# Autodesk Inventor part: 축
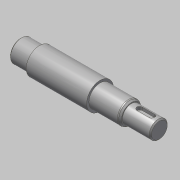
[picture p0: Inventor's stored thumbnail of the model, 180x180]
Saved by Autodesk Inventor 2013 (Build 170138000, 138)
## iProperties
Created: 2016-06
Part Number: 축
Material: 강철, 연강
Document SubType Name: Modeling
Designer: mduedu
Density: 7.86 g/cm^3
Author: mduedu
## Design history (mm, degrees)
sketch "스케치1"
  geometry: L1 (-62, 0)-(62, 0); L2 (-62, 0)-(-62, 10); L3 (-62, 10)-(-45, 10); L4 (-45, 10)-(-45, 12); L5 (-45, 12)-(9, 12); L6 (9, 12)-(9, 10); L7 (9, 10)-(37, 10); L8 (37, 10)-(37, 8); L9 (37, 8)-(62, 8); L10 (62, 8)-(62, 0); 2 further points
  constraints: 20 end point, 5 parallel, 2 perpendicular, 1 coincident, 1 collinear, 1 horizontal, 1 midpoint, 1 vertical
  dimensions: "d0" = 124 distance of L1.start L1.end; "d2" = 16 diameter of L9 L1; "d3" = 20 diameter of L7 L1; "d4" = 24 diameter of L5 L1; "d5" = 20 diameter of L3 L1; "d6" = 17 distance of L2.end L3.end; "d7" = 25 distance of L8.end L9.end; "d8" = 53 distance from line of L5.end L10
revolve "회전1" sketch "스케치1" stored, may be unused: angle "d9" = 90 deg
chamfer "모따기1" distance "d10" = 2; stored, may be unused: second distance "d11" = 2, angle "d12" = 30 deg
fillet "모깎기1" dims "d13" = 2
node "작업 평면1"
sketch "스케치2"
  geometry: L1 (-5, 2.5)-(6, 2.5); L2 (6, -2.5)-(-5, -2.5); L3 (-5, 0)-(6, 0); L4 (-12.5, 8.845)-(-12.5, -8.845) reference; A1 r 2.5 centre (-5, 0) between (-5, 2.5) and (-5, -2.5); A2 r 2.5 centre (6, 0) between (6, -2.5) and (6, 2.5); 1 further point
  constraints: 6 end point, 4 point on circle, 3 tangent, 2 centre point, 2 parallel, 1 horizontal, 1 horizontal alignment
  dimensions: "d14" = 5 distance edge to line of A1 L4; "d15" = 5 distance between parallel lines of L2 L1; "d16" = 16 dimension on A2 A1
extrude "돌출1" cut sketch "스케치2" distance "d17" = 3; taper "d18" = 0 deg
chamfer "모따기2" distance "d19" = 1; stored, may be unused: second distance "d20" = 2, angle "d21" = 30 deg
sketch "스케치3"
  geometry: L1 (-37, -8)-(-61, -8) reference; L2 (-62, -7)-(-62, 7) reference; L3 (-38.5, -8)-(-40, -6.5); L4 (-40, -6.5)-(-40, -8); L5 (-38.5, -8)-(-40, -8); 1 further point
  constraints: 6 end point, 2 point on line, 1 collinear, 1 vertical
  dimensions: "d22" = 45 deg angle of L4 L3; "d23" = 22 distance between parallel lines of L2 L4; "d24" = 3 diameter of L3.start L4
revolve "회전2" stored, may be unused: angle "d25" = 90 deg
node "작업점1"
sketch "스케치4"
  geometry: 1 further point
hole "구멍1" sketch "스케치4" at (0, 0) diameter "d26" = 3.242; stored, may be unused: countersink angle "d30" = 90 deg, drill point angle "d32" = 120 deg; dims "d27" = 8, "d28" = 4, "d29" = 2, "d31" = 11
chamfer "모따기3" distance "d33" = 2; stored, may be unused: second distance "d34" = 2, angle "d35" = 30 deg
node "솔리드1"
